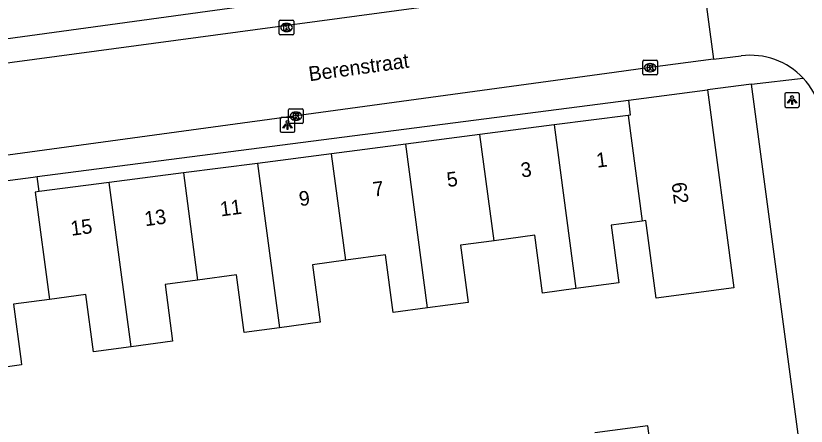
# Model space of a CAD drawing. Extents: x 163150 to 163546, y 380933 to 381635.
# Drawn here: x 163431.2 to 163485.3, y 381288.4 to 381316.4 of the extents above; entities that cross this region are included whole.
import ezdxf

# ---------------------------------------------------------------- set-up
doc = ezdxf.new("R2010")
doc.units = 0
for name, color, linetype in [('IMGEO_Kolk', 7, 'Continuous'), ('IMGEO_Lichtpunt', 7, 'Continuous'), ('IMGEO_Openbare_ruimte_label', 7, 'Continuous'), ('IMGEO_Pand', 7, 'Continuous'), ('IMGEO_Pand_nummerreeks', 7, 'Continuous'), ('IMGEO_Rijbaan_lokaal_open', 7, 'Continuous'), ('IMGEO_Voetpad_open', 7, 'Continuous')]:
    doc.layers.add(name, color=color, linetype=linetype)

msp = doc.modelspace()

# ---------------------------------------------------------------- linework, layer by layer
at = {"layer": 'IMGEO_Kolk'}
for p, q in [((163449.219, 381315.203), (163449.219, 381316.055)), ((163449.294, 381316.129), (163450.146, 381316.129)), ((163449.707, 381315.909), (163449.732, 381315.909)), ((163450.22, 381316.055), (163450.22, 381315.203)), ((163449.73, 381315.349), (163449.705, 381315.349)), ((163450.146, 381315.129), (163449.294, 381315.129)), ((163474.114, 381312.456), (163474.114, 381313.308)), ((163474.189, 381313.382), (163475.041, 381313.382)), ((163475.115, 381313.308), (163475.115, 381312.456)), ((163474.602, 381313.162), (163474.627, 381313.162)), ((163475.041, 381312.382), (163474.189, 381312.382)), ((163474.625, 381312.602), (163474.6, 381312.602)), ((163449.866, 381309.137), (163449.866, 381309.989)), ((163449.941, 381310.063), (163450.793, 381310.063)), ((163450.867, 381309.989), (163450.867, 381309.137)), ((163450.354, 381309.843), (163450.379, 381309.843)), ((163450.793, 381309.063), (163449.941, 381309.063)), ((163450.377, 381309.283), (163450.352, 381309.283))]:
    msp.add_line(p, q, dxfattribs=at)
for points in [[(163449.219, 381315.203), (163449.219, 381316.055)], [(163449.294, 381316.129), (163450.146, 381316.129)], [(163450.22, 381316.055), (163450.22, 381315.203)], [(163449.54, 381315.829), (163449.663, 381315.829), (163449.663, 381315.678), (163449.793, 381315.829), (163449.957, 381315.829), (163449.811, 381315.678), (163449.964, 381315.429), (163449.812, 381315.429), (163449.727, 381315.593), (163449.663, 381315.526), (163449.663, 381315.429), (163449.54, 381315.429), (163449.54, 381315.829)], [(163450.146, 381315.129), (163449.294, 381315.129)], [(163474.114, 381312.456), (163474.114, 381313.308)], [(163474.189, 381313.382), (163475.041, 381313.382)], [(163475.115, 381313.308), (163475.115, 381312.456)], [(163474.435, 381313.082), (163474.558, 381313.082), (163474.558, 381312.931), (163474.688, 381313.082), (163474.852, 381313.082), (163474.706, 381312.931), (163474.859, 381312.682), (163474.707, 381312.682), (163474.622, 381312.846), (163474.558, 381312.779), (163474.558, 381312.682), (163474.435, 381312.682), (163474.435, 381313.082)], [(163475.041, 381312.382), (163474.189, 381312.382)], [(163449.866, 381309.137), (163449.866, 381309.989)], [(163449.941, 381310.063), (163450.793, 381310.063)], [(163450.867, 381309.989), (163450.867, 381309.137)], [(163450.187, 381309.763), (163450.31, 381309.763), (163450.31, 381309.612), (163450.44, 381309.763), (163450.604, 381309.763), (163450.458, 381309.612), (163450.611, 381309.363), (163450.459, 381309.363), (163450.374, 381309.527), (163450.31, 381309.46), (163450.31, 381309.363), (163450.187, 381309.363), (163450.187, 381309.763)], [(163450.793, 381309.063), (163449.941, 381309.063)]]:
    msp.add_lwpolyline(points, dxfattribs=at)
for centre, start, end in [((163449.296, 381316.053), 91.552, 178.448), ((163449.296, 381316.053), 91.552, 178.448), ((163450.144, 381316.053), 1.552, 88.448), ((163450.144, 381316.053), 1.552, 88.448), ((163449.296, 381315.205), 181.552, 268.448), ((163449.296, 381315.205), 181.552, 268.448), ((163450.144, 381315.205), 271.552, 358.448), ((163450.144, 381315.205), 271.552, 358.448), ((163474.191, 381313.306), 91.552, 178.448), ((163474.191, 381313.306), 91.552, 178.448), ((163475.039, 381313.306), 1.552, 88.448), ((163475.039, 381313.306), 1.552, 88.448), ((163474.191, 381312.458), 181.552, 268.448), ((163474.191, 381312.458), 181.552, 268.448), ((163475.039, 381312.458), 271.552, 358.448), ((163475.039, 381312.458), 271.552, 358.448), ((163449.943, 381309.987), 91.552, 178.448), ((163449.943, 381309.987), 91.552, 178.448), ((163450.791, 381309.987), 1.552, 88.448), ((163450.791, 381309.987), 1.552, 88.448), ((163449.943, 381309.139), 181.552, 268.448), ((163449.943, 381309.139), 181.552, 268.448), ((163450.791, 381309.139), 271.552, 358.448), ((163450.791, 381309.139), 271.552, 358.448)]:
    msp.add_arc(centre, 0.0765, start, end, dxfattribs=at)
for centre, major_axis, ratio, start_param, end_param in [((163449.706, 381315.629), (-0.387, 0.002), 0.722429, 4.712389, 7.853982), ((163449.731, 381315.629), (-0.39, 0.002), 0.717154, 1.570796, 4.712389), ((163474.601, 381312.882), (-0.387, 0.002), 0.722429, 4.712389, 7.853982), ((163474.626, 381312.882), (-0.39, 0.002), 0.717154, 1.570796, 4.712389), ((163450.353, 381309.563), (-0.387, 0.002), 0.722429, 4.712389, 7.853982), ((163450.378, 381309.563), (-0.39, 0.002), 0.717154, 1.570796, 4.712389)]:
    msp.add_ellipse(centre, major_axis=major_axis, ratio=ratio, start_param=start_param, end_param=end_param, dxfattribs=at)
at = {"layer": 'IMGEO_Lichtpunt'}
for p, q in [((163483.837, 381311.068), (163483.837, 381310.261)), ((163483.837, 381311.068), (163483.837, 381310.261)), ((163484.739, 381311.163), (163483.931, 381311.163)), ((163484.739, 381311.163), (163483.931, 381311.163)), ((163484.833, 381310.261), (163484.833, 381311.068)), ((163484.833, 381310.261), (163484.833, 381311.068)), ((163483.931, 381310.167), (163484.739, 381310.167)), ((163483.931, 381310.167), (163484.739, 381310.167)), ((163450.19, 381309.464), (163449.382, 381309.464)), ((163450.19, 381309.464), (163449.382, 381309.464)), ((163449.288, 381309.369), (163449.288, 381308.562)), ((163449.288, 381309.369), (163449.288, 381308.562)), ((163450.284, 381308.562), (163450.284, 381309.369)), ((163450.284, 381308.562), (163450.284, 381309.369)), ((163449.382, 381308.468), (163450.19, 381308.468)), ((163449.382, 381308.468), (163450.19, 381308.468))]:
    msp.add_line(p, q, dxfattribs=at)
for points in [[(163484.211, 381310.732), (163484.25, 381310.704), (163484.062, 381310.442), (163484.024, 381310.469), (163484.211, 381310.732)], [(163484.313, 381310.684), (163484.36, 381310.684), (163484.36, 381310.362), (163484.313, 381310.362), (163484.313, 381310.684)], [(163484.423, 381310.704), (163484.461, 381310.731), (163484.648, 381310.469), (163484.609, 381310.441), (163484.423, 381310.704)], [(163449.662, 381309.033), (163449.701, 381309.005), (163449.513, 381308.743), (163449.475, 381308.77), (163449.662, 381309.033)], [(163449.764, 381308.985), (163449.811, 381308.985), (163449.811, 381308.663), (163449.764, 381308.663), (163449.764, 381308.985)], [(163449.874, 381309.005), (163449.912, 381309.032), (163450.099, 381308.77), (163450.06, 381308.742), (163449.874, 381309.005)]]:
    msp.add_lwpolyline(points, dxfattribs=at)
for centre in [(163484.336, 381310.866), (163449.787, 381309.167)]:
    msp.add_circle(centre, 0.0994, dxfattribs=at)
for centre, start, end in [((163483.931, 381311.068), 90, 180), ((163483.931, 381311.068), 90, 180), ((163484.739, 381311.068), 0, 90), ((163484.739, 381311.068), 0, 90), ((163483.931, 381310.261), 180, 270), ((163483.931, 381310.261), 180, 270), ((163484.739, 381310.261), 270, 0), ((163484.739, 381310.261), 270, 360), ((163449.382, 381309.369), 90, 180), ((163449.382, 381309.369), 90, 180), ((163450.19, 381309.369), 0, 90), ((163450.19, 381309.369), 0, 90), ((163449.382, 381308.562), 180, 270), ((163449.382, 381308.562), 180, 270), ((163450.19, 381308.562), 270, 0), ((163450.19, 381308.562), 270, 360)]:
    msp.add_arc(centre, 0.0946, start, end, dxfattribs=at)
at = {"layer": 'IMGEO_Pand'}
for points in [[(163473.125, 381310.664), (163478.534, 381311.364)], [(163478.534, 381311.364), (163480.342, 381297.835), (163475.028, 381297.125), (163474.316, 381302.419), (163474.075, 381302.387)], [(163473.125, 381310.664), (163473.258, 381309.636), (163473.112, 381309.617)], [(163473.112, 381309.617), (163468.036, 381308.961)], [(163473.112, 381309.617), (163474.075, 381302.387)], [(163468.036, 381308.961), (163462.961, 381308.305)], [(163468.036, 381308.961), (163469.526, 381297.777)], [(163462.961, 381308.305), (163457.886, 381307.649)], [(163463.928, 381301.05), (163462.961, 381308.305)], [(163457.886, 381307.649), (163452.809, 381306.992)], [(163459.379, 381296.447), (163457.886, 381307.649)], [(163452.809, 381306.992), (163447.734, 381306.336)], [(163453.78, 381299.711), (163452.809, 381306.992)], [(163447.734, 381306.336), (163442.658, 381305.68)], [(163447.734, 381306.336), (163449.233, 381295.095)], [(163442.658, 381305.68), (163437.582, 381305.024)], [(163442.658, 381305.68), (163443.636, 381298.348)], [(163427.187, 381304.722), (163427.294, 381304.736), (163432.37, 381305.392), (163432.643, 381305.427)], [(163432.775, 381304.402), (163432.643, 381305.427)], [(163437.582, 381305.024), (163432.775, 381304.402)], [(163439.08, 381293.787), (163437.582, 381305.024)], [(163432.775, 381304.402), (163432.507, 381304.367), (163433.485, 381297.033)], [(163474.075, 381302.387), (163471.936, 381302.1), (163472.463, 381298.171), (163469.526, 381297.777)], [(163469.526, 381297.777), (163467.24, 381297.471), (163466.71, 381301.423), (163463.928, 381301.05)], [(163463.928, 381301.05), (163461.638, 381300.743), (163462.164, 381296.82), (163459.379, 381296.447)], [(163453.78, 381299.711), (163451.502, 381299.405), (163452.03, 381295.47), (163449.233, 381295.095)], [(163459.379, 381296.447), (163457.024, 381296.131), (163456.495, 381300.075), (163453.78, 381299.711)], [(163449.233, 381295.095), (163446.828, 381294.772), (163446.3, 381298.705), (163443.636, 381298.348)], [(163443.636, 381298.348), (163441.403, 381298.048), (163441.924, 381294.169), (163439.08, 381293.787)], [(163433.485, 381297.033), (163431.028, 381296.704), (163431.554, 381292.781), (163431.584, 381292.558), (163428.967, 381292.196)], [(163439.08, 381293.787), (163436.512, 381293.443), (163435.986, 381297.368), (163433.485, 381297.033)], [(163474.838, 381285.471), (163474.457, 381288.388), (163470.84, 381287.917)]]:
    msp.add_lwpolyline(points, dxfattribs=at)
at = {"layer": 'IMGEO_Rijbaan_lokaal_open'}
for points in [[(163422.756, 381312.154), (163478.14, 381319.616)], [(163478.14, 381319.616), (163478.952, 381313.454)], [(163478.952, 381313.454), (163474.614, 381312.883), (163472.145, 381312.545), (163423.08, 381305.875), (163422.932, 381305.852)], [(163478.952, 381313.454), (163480.848, 381313.687)]]:
    msp.add_lwpolyline(points, dxfattribs=at)
for centre, radius, start, end in [((163481.478, 381308.776), 4.951, 43.0173, 97.3134), ((163481.488, 381308.784), 4.939, 15.8417, 43.0298)]:
    msp.add_arc(centre, radius, start, end, dxfattribs=at)
at = {"layer": 'IMGEO_Voetpad_open'}
for points in [[(163424.95, 381314.09), (163471.819, 381320.534), (163475.188, 381320.95)], [(163481.558, 381311.755), (163485.098, 381312.154)], [(163481.558, 381311.755), (163478.534, 381311.364)], [(163484.876, 381286.803), (163481.558, 381311.755)], [(163432.643, 381305.427), (163473.125, 381310.664)]]:
    msp.add_lwpolyline(points, dxfattribs=at)

# ---------------------------------------------------------------- texts
at = {"layer": 'IMGEO_Openbare_ruimte_label'}
msp.add_text('Berenstraat', height=1, rotation=7.8142, dxfattribs=at).set_placement((163451.301, 381311.949))
at = {"layer": 'IMGEO_Pand_nummerreeks'}
for s, rotation, p in [('1', 7.3668, (163470.989, 381306.035)), ('3', 7.3668, (163465.815, 381305.366)), ('5', 7.3668, (163460.755, 381304.711)), ('7', 7.3668, (163455.695, 381304.057)), ('62', 277.6118, (163476.077, 381304.986)), ('9', 7.3668, (163450.634, 381303.403)), ('11', 7.3668, (163445.231, 381302.706)), ('13', 7.3668, (163440.057, 381302.036)), ('15', 7.3682, (163434.997, 381301.381))]:
    msp.add_text(s, height=1, rotation=rotation, dxfattribs=at).set_placement(p)

doc.saveas('drawing.dxf')
